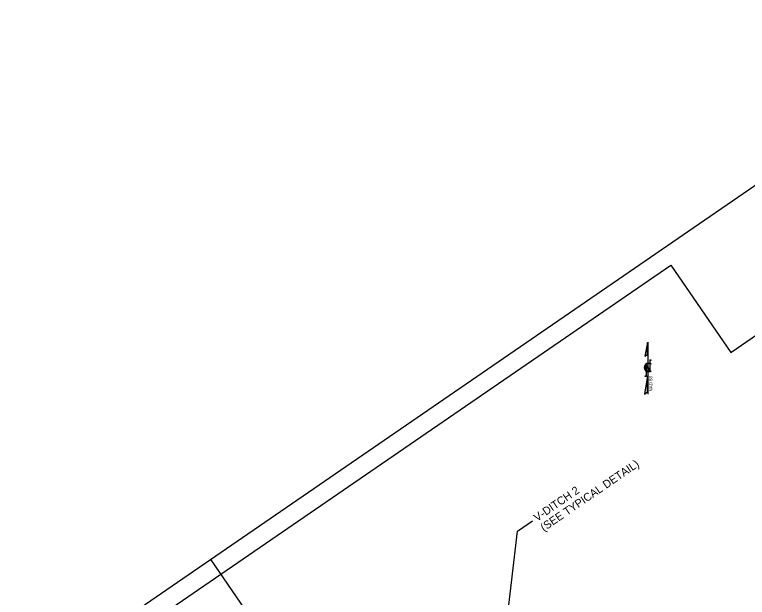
# Model space of a CAD drawing. Extents: x 2385901 to 2398119, y 552503 to 560016.
# Drawn here: x 2396288 to 2397204, y 559260 to 559988 of the extents above; entities that cross this region are included whole.
import ezdxf

# ---------------------------------------------------------------- set-up
doc = ezdxf.new("R2010")
doc.units = 0
for name, color, linetype in [('Old_Level_18', 7, 'Continuous'), ('Old_Level_25', 7, 'Continuous'), ('Old_Level_34', 7, 'Continuous'), ('Old_Level_40', 7, 'Continuous'), ('Old_Level_50', 7, 'Continuous')]:
    doc.layers.add(name, color=color, linetype=linetype)

msp = doc.modelspace()

# ---------------------------------------------------------------- linework, layer by layer
at = {"layer": 'Old_Level_18'}
msp.add_lwpolyline([(2397524.57, 559988.17), (2396288.13, 559138.87), (2396882.63, 558273.38), (2398119.05, 559122.67)], close=True, dxfattribs=at)
at = {"layer": 'Old_Level_25'}
for p, q in [((2397079.49, 559514.2), (2397079.49, 559579.2)), ((2397081.94, 559545.32), (2397076.97, 559550.29)), ((2397076.97, 559550.29), (2397076.97, 559536.73)), ((2397081.94, 559544.83), (2397076.97, 559549.8)), ((2397076.97, 559549.8), (2397076.97, 559548.58)), ((2397081.94, 559543.61), (2397076.97, 559548.58)), ((2397076.97, 559548.58), (2397081.94, 559543.61)), ((2397081.94, 559543.24), (2397076.97, 559548.21)), ((2397081.94, 559556.58), (2397081.94, 559543.24)), ((2397083.78, 559551.61), (2397083.85, 559551.56)), ((2397081.94, 559543.61), (2397081.94, 559544.83))]:
    msp.add_line(p, q, dxfattribs=at)
for points in [[(2397079.04, 559578.63), (2397075.33, 559561.75), (2397079.04, 559563.63)], [(2397078.96, 559537.1), (2397075.28, 559514.2), (2397078.96, 559517.1)]]:
    msp.add_lwpolyline(points, close=True, dxfattribs=at)
for centre in [(2397082.47, 559556.57), (2397076.44, 559536.71)]:
    msp.add_circle(centre, 0.53, dxfattribs=at)
for centre, radius, start, end in [((2397080.19, 559547.51), 5.46, 47.84002, 312.39406), ((2397080.71, 559547.51), 5.12, 53.09504, 308.62871)]:
    msp.add_arc(centre, radius, start, end, dxfattribs=at)
at = {"layer": 'Old_Level_34'}
msp.add_lwpolyline([(2396899.03, 559193.51), (2396916.34, 559343), (2396935.1, 559355.88)], dxfattribs=at)
at = {"layer": 'Old_Level_40'}
msp.add_line((2396533.27, 559307.25), (2396710.27, 559049.57), dxfattribs=at)
at = {"layer": 'Old_Level_50'}
msp.add_lwpolyline([(2396323.89, 559136.9), (2397107.84, 559675.39), (2397182.92, 559566.09), (2397427.9, 559734.37), (2397466.74, 559677.83), (2397606.19, 559773.62), (2398061.84, 559110.28), (2396893.45, 558307.72)], close=True, dxfattribs=at)

# ---------------------------------------------------------------- texts
at = {"layer": 'Old_Level_25'}
msp.add_text('NAD 83', height=4, rotation=90, dxfattribs=at).set_placement((2397084.84, 559517.51))
at = {"layer": 'Old_Level_34'}
for s, p in [('(SEE TYPICAL DETAIL)', (2396949.38, 559342.31)), ('V-DITCH 2', (2396940.89, 559354.67))]:
    msp.add_text(s, height=10, rotation=34.48491, dxfattribs=at).set_placement(p)

doc.saveas('drawing.dxf')
